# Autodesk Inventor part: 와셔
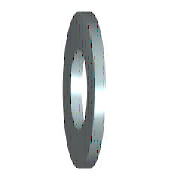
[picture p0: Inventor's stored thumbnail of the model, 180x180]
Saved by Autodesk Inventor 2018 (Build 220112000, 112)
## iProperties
IsCustomPart: 1
Created: 2012-02
Part Number: 와셔
Material: 강철, 연강
Description: 평면 와셔
Document SubType Name: Modeling
Standard: KS B 1326
Designer: mduedu
Standards Organization: KS
Language: ko-KR
Size Designation: 8x15.5
Categories: <MemberInstance><Categories><Category DisplayName="조임쇠" InternalName="e4da775c-781d-43d5-af7c-5136215cf5a6" Mnemonic="FSTN"><Category DisplayName="와셔" InternalN
Density: 1 g/cm^3
Appearance: 주황색
Author: mduedu
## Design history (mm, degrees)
sketch "스케치"
  geometry: C1 r 7.75 at (0, 0); C2 r 4.2 at (0, 0); 1 further point
  constraints: 2 centre point, 2 coincident
  dimensions: "d0" = 8.4 diameter of C2 (= SD1); "d1" = 15.5 diameter of C1 (= SD2)
extrude "본체" new body sketch "스케치" distance "d2" = 1.6 (= SD); taper "d3" = 0 deg
workaxis "Work Axis1"
workplane "Work Plane1"
body "Solid1"
other parameters: "SD1" = 8.4 [user parameter; used in 1 equation term], "SD2" = 15.5 [user parameter; used in 1 equation term], "SD" = 1.6 [user parameter; used in 1 equation term], "d4" = 0, "d5" = 0, "d6" = 0, "d7" = 0, "NND" = 8 [user parameter]
